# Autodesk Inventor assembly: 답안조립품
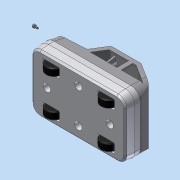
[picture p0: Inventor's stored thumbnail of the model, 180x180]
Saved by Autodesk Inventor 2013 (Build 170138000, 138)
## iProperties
Created: 2015-05
Part Number: 답안조립품
Document SubType Name: Assembly
Designer: Administrator
Author: Administrator
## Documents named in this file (7)
- C:\Users\Administrator\Desktop\450508V1048\답안조립품.iam
- C:\Users\Administrator\Desktop\450508V1048\본체.ipt
- C:\Users\Administrator\Desktop\450508V1048\M2x4.ipt
- C:\Users\Administrator\Desktop\450508V1048\M4x10.ipt
- C:\Users\Administrator\Desktop\450508V1048\바퀴.ipt
- C:\Users\Administrator\Desktop\450508V1048\바퀴고정부.ipt
- C:\Users\Administrator\Desktop\450508V1048\커버.ipt
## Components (2 placed, 2 different names)
1. M2x4:1
2. M4x10:1
